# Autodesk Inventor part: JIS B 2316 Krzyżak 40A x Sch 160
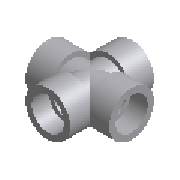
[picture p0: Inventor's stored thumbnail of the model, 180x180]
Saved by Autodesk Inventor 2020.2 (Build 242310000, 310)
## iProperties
Manager: www.cadconsulting.pl
Company: Fabian Stasiak CAD Consulting
NAME: PIPING: JIS B 2316 Cross
DATA: <meta><inlinegroups number="2" deflen="4.62"></inlinegroups><connections number="4"></connections><angles><a>1.57079632679489</a><a>3.14159265358979</a><a>1.570
IsCustomPart: 0
Created: 2016-02
Part Number: JIS B 2316 Krzyżak 40A x Sch 160
Material: Stal
Description: Krzyżak
Document SubType Name: Modeling
Standard: JIS B 2316
Designer: F.Stasiak
Standards Organization: JIS
Language: pl-PL
Size Designation: 40A x Sch 160
Categories: <MemberInstance><Categories><Category DisplayName="Rury cienko- i grubościenne" InternalName="4347fa0f-2144-441d-94cd-e3e15c92b736" Mnemonic="TUBEANDPIPE"><Cate
Density: 1 g/cm^3
Appearance: Płyta
Catalog Web Link: www.expertbooks.pl
Author: F.Stasiak
Subject: Zbiór ćwiczeń. Autodesk Inventor 2020. Kurs Professional
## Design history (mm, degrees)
sketch "Sketch1"
  geometry: L1 (0, 0)-(50.8, 0); L2 (50.8, 0)-(50.8, 25); L3 (20.5, 32.35)-(0, 32.35); L4 (0, 24.55)-(0, 0); L5 (12.7, 24.55)-(12.7, 17.2); L6 (12.7, 17.2)-(50.8, 17.2); L7 (20.5, 32.35)-(20.5, 25); L8 (20.5, 25)-(50.8, 25); L9 (0, 24.55)-(0, 32.35); L10 (88.9, 17.2)-(50.8, 17.2); L11 (101.6, 24.55)-(101.6, 32.35); L12 (81.1, 32.35)-(101.6, 32.35); L13 (81.1, 32.35)-(81.1, 25); L14 (81.1, 25)-(50.8, 25); L15 (101.6, 24.55)-(101.6, 0); L16 (101.6, 0)-(50.8, 0); L17 (0, 24.55)-(12.7, 24.55); L18 (101.6, 24.55)-(88.9, 24.55); L19 (88.9, 24.55)-(88.9, 17.2); L20 (0, 24.55)-(0, 0); L21 (0, 0)-(101.6, 0); L22 (101.6, 0)-(101.6, 24.55); L23 (12.7, 17.2)-(12.7, 0); L24 (88.9, 17.2)-(88.9, 0); C1 r 3.9 at (16.6, 28.45); C2 r 3.9 at (16.6, 21.1)
  constraints: 48 end point, 7 perpendicular, 7 symmetric about line, 7 tangent, 4 parallel, 3 point on line, 2 centre point, 2 horizontal, 1 collinear, 1 equal radius, 9 other
  dimensions: "d0" = 34.4 diameter of L6 L1 (= D); "d1" = 12.7 distance between parallel lines of L9 L5 (= C1); "d2" = 38.1 distance between parallel lines of L2 L5 (= G); "d6" = 49.1 diameter of L4.start L1 (= S); "d7" = 7.8 distance of L4.start L3.end (= T)
revolve "Revolve1" stored, may be unused: angle "d8" = 90 deg
sketch "Sketch2"
  geometry: L1 (0, 0)-(-50.8, 0) reference; L2 (-50.8, 0)-(-50.8, 50.8); L3 (-50.8, 50.8)-(-75.35, 50.8); L4 (-83.15, 50.8)-(-83.15, 30.3); L5 (-68, 0)-(-50.8, 0); L6 (-75.35, 38.1)-(-68, 38.1); L7 (-68, 38.1)-(-68, 0); L8 (-75.35, 50.8)-(-83.15, 50.8); L9 (-83.15, 30.3)-(-75.8, 30.3); L10 (-75.8, 30.3)-(-75.8, 0); L11 (-68, 0)-(-75.8, 0); L12 (-75.35, 50.8)-(-75.35, 38.1); L13 (-75.35, 50.8)-(-50.8, 50.8); L14 (-50.8, 50.8)-(-50.8, 0); L15 (-50.8, 0)-(-68, 0); L16 (-50.8, -50.8)-(-75.35, -50.8); L17 (-83.15, -50.8)-(-83.15, -30.3); L18 (-75.35, -50.8)-(-83.15, -50.8); L19 (-75.35, -50.8)-(-75.35, -38.1); L20 (-75.35, -50.8)-(-50.8, -50.8); L21 (-75.35, -38.1)-(-68, -38.1); L22 (-83.15, -30.3)-(-75.8, -30.3); L23 (-75.8, -30.3)-(-75.8, 0); L24 (-50.8, 0)-(-50.8, -50.8); L25 (-50.8, -50.8)-(-50.8, 0); L26 (-68, -38.1)-(-68, 0); L27 (-68, -38.1)-(-50.8, -38.1); L28 (-68, 38.1)-(-50.8, 38.1); C1 r 3.9 at (-79.25, 34.2); C2 r 3.9 at (-71.9, 34.2); C3 r 3.9 at (-79.25, -34.2); C4 r 3.9 at (-71.9, -34.2)
  constraints: 54 end point, 9 symmetric about line, 8 perpendicular, 8 tangent, 4 centre point, 2 parallel, 2 point on line, 1 vertical, 13 other
  dimensions: "d3" = 34.4 diameter of L7 L2 (= D); "d4" = 12.7 distance between parallel lines of L6 L8 (= C1); "d5" = 38.1 distance between parallel lines of L6 L5 (= G); "d9" = 49.1 diameter of L3.end L2 (= S); "d10" = 7.8 distance of L3.end L4.start (= T)
revolve "Revolve2" stored, may be unused: angle "d18" = 90 deg
revolve "Revolve3" stored, may be unused: angle "d57" = 90 deg
revolve "Revolve4" stored, may be unused: angle "d58" = 90 deg
workpoint "Work Point1"
workpoint "Work Point2"
workpoint "Work Point3"
workpoint "Work Point4"
workaxis "Work Axis1"
workpoint "Work Point5"
workaxis "Work Axis2"
workpoint "Work Point6"
workaxis "Work Axis3"
workpoint "Work Point7"
workaxis "Work Axis4"
workpoint "Work Point8"
body "Solid1"
other parameters: "S" = 49.1 [user parameter; used in 2 equation terms], "D" = 34.4 [user parameter; used in 2 equation terms], "T" = 7.8 [user parameter; used in 2 equation terms], "C1" = 12.7 [user parameter; used in 2 equation terms], "G" = 38.1 [user parameter; used in 2 equation terms], "Size_Designation" = 12.345 [user parameter]
